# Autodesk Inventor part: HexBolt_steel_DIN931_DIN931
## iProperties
Author: Jørgen Albe Bjørnes
Shininess: 25.0
PropertySet Name: _Private Model Information
Created: 2001-01
Part Number: HexBolt_steel_DIN931_DIN931
Document SubType Name: Modeling
Designer: Jørgen Albe Bjørnes
Material: 8.8
Description: Hex-head bolt M8x30
Vendor: DIN 933 / DIN EN 24 017
Control State: 0
Master: False
Checked Out: False
PropertySet Name: Design Tracking Control
Density: 0.0
Volumn: 0.0
Area: 0.0
PropertySet Name: Model Information
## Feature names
1. Extrusion1
2. Extrusion2
3. Revolution2
4. Chamfer1
5. Extrusion3
